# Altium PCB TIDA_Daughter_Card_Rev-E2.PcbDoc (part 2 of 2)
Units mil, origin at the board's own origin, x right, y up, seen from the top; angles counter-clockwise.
Board outline 3149.06 x 866.14 mil, 6 copper layers (L1-Top Layer, L2-GND1, L3-SIG1, L4-PWR, L5-GND2, L6-Bottom Layer), stack 0 mil thick; 80 components, 50 nets, 307 pads, 118 vias.
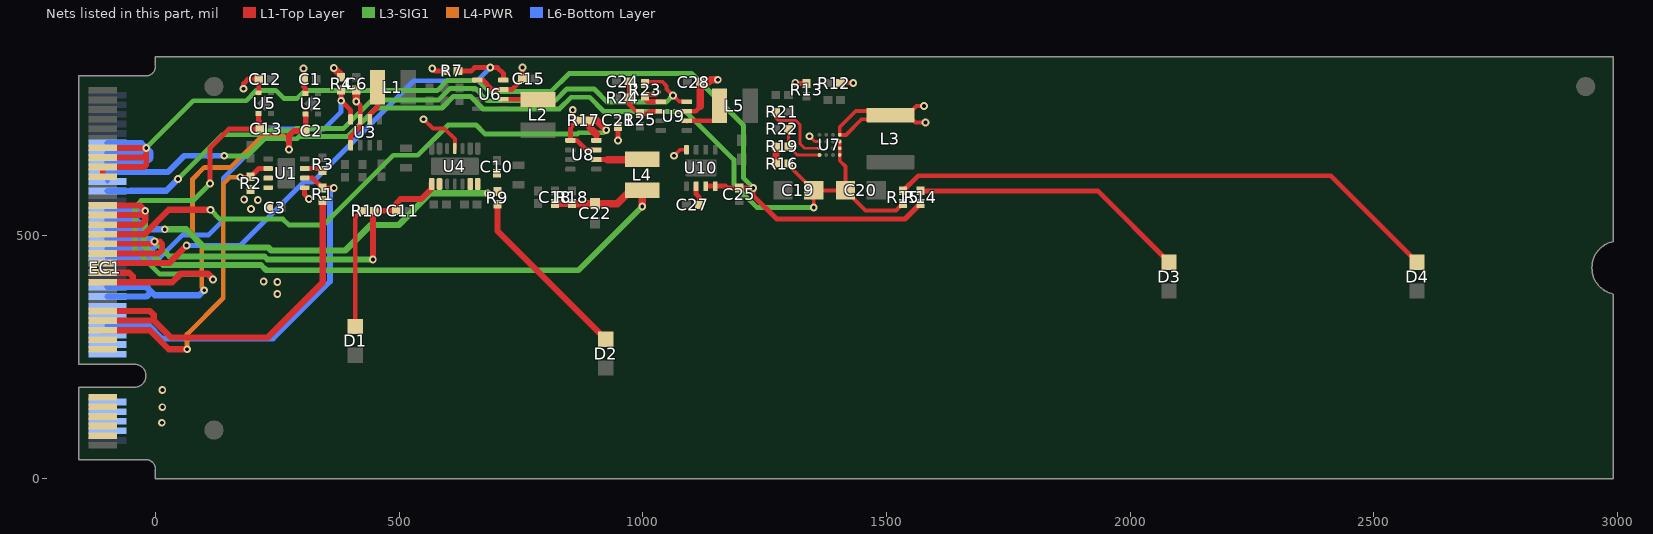
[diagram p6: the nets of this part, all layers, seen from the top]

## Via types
v1: diameter 16, hole 8, L1-Top Layer to L6-Bottom Layer, tented both sides, 111 vias
v2: diameter 19.68, hole 7.87, L1-Top Layer to L6-Bottom Layer, 7 vias

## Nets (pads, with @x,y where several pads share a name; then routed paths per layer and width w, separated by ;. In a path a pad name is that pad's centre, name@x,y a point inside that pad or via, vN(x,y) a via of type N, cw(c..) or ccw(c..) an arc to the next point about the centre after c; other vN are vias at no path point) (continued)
NetC24_2: C24.2 R24.1 R25.2 U9.2 | length 121.8
  L1-Top Layer w9: C24.2@971.99,815 R24.1@971.99,782 971.99,768.01 990.42,749.58 R25.2@994.57,749.58 1009.58,749.58 1014.31,754.31 U9.2@1037.22,754.31
NetC27_1: C27.1 U10.6 | length 41.3
  L1-Top Layer w10: U10.6@1109.44,600.6 1109.44,584.56 1115.99,578.01 C27.1@1115.99,562
NetD1_1: D1.1 R10.1 | length 242.9
  L1-Top Layer w10: D1.1@410,312.53 410,536.99 R10.1@423.01,550
NetD2_1: D2.1 R9.1 | length 368.9
  L1-Top Layer w12: R9.1@701.6,563.34 701.6,508.93 D2.1@924,286.53
NetD3_1: D3.1 R14.1 | length 570.7
  L1-Top Layer w10: R14.1@1570,591 1933.53,591 D3.1@2080,444.53
NetD4_1: D4.1 R15.1 | length 1141.2
  L1-Top Layer w10: R15.1@1534.12,591.05 1565.07,622 2411.53,622 D4.1@2589,444.53
NetL1_1: L1.1 U3.6 | length 72.9
  L1-Top Layer w10: U3.6@439.84,737.57 439.84,747.84 455.5,763.5 L1.1@455.5,804
NetL2_1: L2.1 U6.6 | length 71.4
  L1-Top Layer w10: U6.6@713.79,779 784.5,779 L2.1@785,778.5
NetL4_1: L4.1 U8.6 | length 94.5
  L1-Top Layer w10: U8.6@904.75,655.21 927.79,655.21 928,655
  L1-Top Layer w15: 928,655 998.5,655 L4.1@999,655.5
NetL5_1: L5.1 U9.6 | length 91.4
  L1-Top Layer w10: U9.6@1090.37,734.63 1090.61,734.87 1145.65,734.87 1157.5,746.73 L5.1@1157.5,766
NetR3_2: R3.2 U1.7 | length 38.6
  L1-Top Layer w10: U1.7@306,636.83 339.17,636.83 R3.2@343,633.01
NetR16_1: R16.1 R19.2 | length 35
  L1-Top Layer w15: R16.1@1273.45,647 R19.2@1273.45,682
NetR19_1: R19.1 R22.2 U7.A1@1362.83,664.58 | length 106.8
  L1-Top Layer w6: R22.2@1299,718 1299,682.44 R19.1@1299.43,682 1316.86,664.58 U7.A1@1362.83,664.58
NetR21_2: R21.2 U7.A2@1362.83,678.36 | length 150.8
  L1-Top Layer w6: R21.2@1273.02,753 1273.02,740.98 1279,735 1314.28,735 1323,726.28 1323,687 1331.64,678.36 U7.A2@1362.83,678.36
PG_VCC_3DNAND: EC1.54 R23.1 U9.8 | length 1392.4
  L1-Top Layer w8: R23.1@1005,810.99 1008.88,814.87 1040.13,814.87 1049.02,805.98 1049.02,799.87 v1(1062,786.89) 1074.89,774 U9.8@1090.37,774
  L3-SIG1 w10: v1(46,615) 137,706 210.28,706 217.98,713.7 283.82,713.7 288.69,718.57 385.66,718.57 444.78,777.7 580.95,777.7 604.52,801.27 655.8,801.27 681.07,776 820,776 844,800 900,800 926.87,773.13 1048.23,773.13 v1(1062,786.89)
  L6-Bottom Layer w13: EC1.54@-98.43,590.55 -51.89,590.55 -51.36,591.07 22.07,591.07 v1(46,615)
PG_VCC_DDR3: EC1.39 R7.1 U6.8 | length 1075.7
  L1-Top Layer w10: R7.1@620.99,837 647.81,837 654.81,844 v1(687,844) 701.76,844 713.79,831.97 U6.8@713.79,818.37
  L1-Top Layer w13: EC1.39@-108.27,442.91 27.91,442.91 v1(64,479)
  L6-Bottom Layer w10: v1(64,479) 174.39,479 304.51,609.13 322.66,609.13 530.53,817 660,817 v1(687,844)
PG_VCC_IO_3DNAND: EC1.45 R17.1 U8.8 | length 1250.2
  L1-Top Layer w10: U8.8@904.75,694.58 904.75,707.38
  L1-Top Layer w13: EC1.45@-108.27,501.97 -22.67,501.97 27.36,552 v1(113,552)
  L1-Top Layer w15: 904.75,707.38 891.74,720.39 R17.1@891.74,735.53 905.47,735.53 v1(925,716)
  L3-SIG1 w10: v1(113,552) 132,533 261.48,533 273.35,521.13 345.13,521.13 488,664 538.26,664 600.39,726.13 657.87,726.13 676,708 866,708 868.33,710.33 919.33,710.33 v1(925,716)
PG_VCORE_SOC: EC1.40 R4.1 U3.8 | length 745.6
  L1-Top Layer w10: R4.1@381,798.01 v1(381,775.92) 400.47,756.44 U3.8@400.47,737.57
  L6-Bottom Layer w10: EC1.40@-98.43,452.76 7.76,452.76 55,500 108.52,500 139.13,530.61 139.13,616.65 240.48,718 346,718 381,753 v1(381,775.92)
SSD_EN: EC1.25 R2.1 U1.2 | length 664.8
  L1-Top Layer w10: v1(174,619) 194.02,619 R2.1@195,619.98 211.85,636.83 U1.2@231.2,636.83
  L1-Top Layer w13: EC1.25@-108.27,305.12 -12.11,305.11 27,266 v1(65,266)
  L4-PWR w10: v1(65,266) 65,297 139,371 139,605.52 152.48,619 v1(174,619)
SSD_FLTb: EC1.26 R1.1 U1.6 | length 779.7
  L1-Top Layer w10: U1.6@306,617.15 322.84,617.15 R1.1@343,596.99 v1(366.01,596.99)
  L6-Bottom Layer w12: EC1.26@-98.43,314.96 -13.96,314.96 13,288 241,288 358,405 358,588.98 v1(366.01,596.99)
VAUX: EC1.27 EC1.29 R1.2 | length 799.9
  L1-Top Layer w13: EC1.27@-108.27,324.8 -3.8,324.8 ; EC1.29@-108.27,344.49 -11.93,344.49 -3.8,336.36 -3.8,324.8 ; R1.2@343,571.01 343,403 230,290 31,290 -3.8,324.8
VCC_3DNAND: C25.1 EC1.57 EC1.59 EC1.60 EC1.61 EC1.62 EC1.63 EC1.64 R14.2 U10.7 U10.8 | length 2601.6
  L1-Top Layer w10: U10.7@1129.13,600.6 U10.8@1148.81,600.6 1169.4,600.6 1173.01,596.99 C25.1@1198,596.99 v1(1226.7,596.99) 1226.7,581.3 1274.87,533.13 1538.11,533.13 R14.2@1570,565.02
  L1-Top Layer w12: EC1.57@-108.27,620.08 EC1.59@-108.27,639.76 -23.24,639.76 -19,644 -19,657.96 ; EC1.61@-108.27,659.45 -20.49,659.45 -19,657.96 ; EC1.63@-108.27,679.13 v1(-19,679.13) -19,657.96
  L3-SIG1 w10: v1(-19,679.13) 77.87,776 185.83,776 206.89,797.06 246.7,797.06 263.15,780.61 290.49,780.61 306.67,796.79 577.83,796.79 598.02,816.97 662.3,816.97 684.28,795 812,795 848.87,831.87 1100.13,831.87 1207,725 1207,616.7 v1(1226.7,596.99)
  L6-Bottom Layer w12: EC1.60@-98.43,649.61 -18.39,649.61 -9.87,658.13 -9.87,670.01 v1(-19,679.13) ; EC1.62@-98.43,669.29 -28.84,669.29 v1(-19,679.13) ; EC1.64@-98.43,688.98 -28.84,688.98 v1(-19,679.13)
VCC_DDR3: C10.1 EC1.46 EC1.48 R9.2 U4.13 U4.14 | length 929.1
  L1-Top Layer w15: C10.1@700.36,626.58 C10.1@700.79,627.01
  L3-SIG1 w13: v1(19,512) 63,512 100.4,474.6 231.31,474.6 237.39,468.53 389.53,468.53 442,521 499,521 564,586 v1(682,586)
  L6-Bottom Layer w13: EC1.46@-98.43,511.81 -98.43,512 -32.3,512 ; EC1.48@-98.43,531.5 -39.79,531.5 -32.3,524 -32.3,512 ; v1(19,512) -32.3,512
VCC_IO_3DNAND: C18.1 C22.1 EC1.47 EC1.49 EC1.50 EC1.51 L4.2 R18.2 | length 1766.4
  L1-Top Layer w13: EC1.47@-108.27,521.65 -29.43,521.65 -21,530.09 v1(-21,550) ; EC1.49@-108.27,541.34 -29.66,541.34 v1(-21,550) ; EC1.51@-108.27,561.02 -32.02,561.02 v1(-21,550)
  L1-Top Layer w15: C18.1@820,565.01 R18.2@855,565.01 855.32,564.68 C22.1@902,564.68 947.56,564.68 975.38,592.5 L4.2@999,592.5 v1(999,559)
  L3-SIG1 w12: v1(-21,550) -21,498.93 -23.87,496.06 -23.87,477.94 15.37,438.7 216.44,438.7 227.02,428.13 868.13,428.13 v1(999,559)
  L6-Bottom Layer w13: EC1.50@-98.43,551.18 -22.18,551.18 v1(-21,550)
VCC_IO_SOC: C13.1 EC1.35 EC1.37 U5.1 | length 987.7
  L1-Top Layer w10: v1(112,606) 112,679 151,718 C13.1@214.01,718 214.01,733.74 211.31,736.44 U5.1@211.31,750.01
  L1-Top Layer w13: EC1.35@-108.27,403.54 -47,403.54 ; EC1.37@-108.27,423.23 -54.23,423.23 -47,416 -47,403.54 ; v1(118,409) 118,410 106.63,421.37 52.37,421.37 34.54,403.54 -47,403.54
  L3-SIG1 w10: v1(112,606) 77,571 -29.52,571 -41.87,558.65 -41.87,470.91 9.03,420 108,420 118,410 v1(118,409)
VCC_SOC: C2.1 EC1.32 EC1.34 U2.1 | length 898
  L1-Top Layer w12: v1(274,676) 274,704 283.82,713.82 C2.1@306.85,713.82 308.24,715.2 U2.1@308.24,748.75
  L4-PWR w10: v1(100.13,386.94) 94.87,392.19 94.87,480.13 76,499 76,615 100,639 154.52,639 219.39,703.87 262.13,703.87 274,692 v1(274,676)
  L6-Bottom Layer w13: EC1.32@-98.43,374.02 -18.42,374.02 -8.63,383.81 ; EC1.34@-98.43,393.7 -18.52,393.7 -8.63,383.81 ; v1(100.13,386.94) 89.82,376.63 -1.44,376.63 -8.63,383.81
VCORE_SOC: C11.1 EC1.41 EC1.42 EC1.43 EC1.44 R10.2 U4.8 U4.9 | length 1203.3
  L1-Top Layer w12: EC1.41@-108.27,462.6 6.6,462.6 14,470 14,482 9,487 v1(-2,487) -6.72,482.28 EC1.43@-108.27,482.28 ; v1(446,450) 446,550 R10.2@448.99,550 ; R10.2@448.99,550 C11.1@494.01,550 494.01,565.01 503,574 545,574 U4.8@566.54,595.54 ; U4.8@566.54,606.58 U4.8@566.54,595.54 ; U4.8@567.01,605 567.01,596.01 U4.8@566.54,595.54
  L3-SIG1 w12: v1(-2,487) 28.6,456.4 223.77,456.4 230.17,450 v1(446,450)
  L6-Bottom Layer w12: EC1.42@-98.43,472.44 -5.56,472.44 -2,476 v1(-2,487) -7.13,492.13 EC1.44@-98.43,492.13
VIN: C3.1 EC1.3 EC1.4 EC1.5 EC1.6 EC1.7 EC1.8 EC1.9 EC1.10 EC1.11 EC1.20 EC1.21 EC1.22 EC1.23 EC1.24 R2.2 U1.3 U1.4
  other v1: 13,115 14,147 14,182 196,554 210,572 182,573
VPP_3DNAND: C19.1 C20.1 EC1.56 EC1.58 R15.2 R16.2 U7.D1@1404.17,664.58 U7.D2@1404.17,678.36 U7.D3@1404.17,692.13 | length 2100.3
  L1-Top Layer w8: R16.2@1299.43,647 1299.43,643.51 C19.1@1350.94,592 ; v1(1350.94,556.94) C19.1@1350.94,592 ; U7.D3@1404.17,692.13 U7.D2@1404.17,678.36 U7.D1@1404.17,664.58 1404.17,652.82 1415.95,641.04 C20.1@1415.95,592 ; R15.2@1534.12,565.06 1520.05,551 1456.95,551 C20.1@1415.95,592 ; C19.1@1350.94,592 C20.1@1415.95,592
  L3-SIG1 w10: v1(141,663) 141.89,662.11 188.59,662.11 224.48,698 290.32,698 295.19,702.87 394.87,702.87 453,761 587.86,761 611.44,784.57 646.56,784.57 672.14,759 828.81,759 852.81,783 891,783 920.43,753.57 1088.43,753.57 1187,655 1187,604 1234.06,556.94 v1(1350.94,556.94)
  L6-Bottom Layer w8: EC1.56@-98.43,610.24 EC1.58@-98.43,629.92
  L6-Bottom Layer w12: EC1.58@-98.43,629.92 25.92,629.92 59,663 v1(141,663)
VSYS: C1.1 C6.1 C12.1 C15.1 C21.1 C28.1 EC1.28 EC1.30 L3.1 R4.2 R7.2 R12.2 R13.1 R17.2 R23.2 U1.5 U2.4 U3.1 U3.7 U4.4 U5.4 U6.1 U6.7 U7.A3@1362.83,692.13 U7.D4@1404.17,705.91 U8.1 U8.7 U9.1 U9.7 U10.4 | length 1405.1
  L1-Top Layer w6: v1(1342.15,703) 1353.02,692.13 U7.A3@1362.83,692.13
  L1-Top Layer w8: v1(550,738) 569.3,718.7 592.64,718.7 614.25,697.09 U4.4@614.25,677.83 ; v1(1064,663) 1076.4,675.4 U10.4@1089.76,675.4 ; R12.2@1406,812 v1(1432,812) ; v1(1577,765) 1562,765 L3.1@1543.23,746.23 ; v1(1580,731) 1560,731 1544.77,746.23 L3.1@1543.23,746.23 ; L3.1@1508,746.23 L3.1@1543.23,746.23 ; L3.1@1508,746.23 1499.23,755 1437,755 1404.17,722.17 U7.D4@1404.17,705.91 1416.91,705.91 1449,738 1499.77,738 L3.1@1508,746.23
  L1-Top Layer w10: v1(180.8,800.48) 180.8,810.95 190.33,820.48 C12.1@211.8,820.48 211.8,792.63 U5.4@211.31,792.13 ; v1(304.01,841.84) C1.1@304.01,820 304.01,804.65 308.24,800.43 U2.4@308.24,790.87 ; U1.5@306,597.46 306,583 v1(315,574) ; U3.1@400.47,684.43 400.47,702.47 420.16,722.16 U3.7@420.16,737.57 420.16,766.28 v1(412,774.44) ; v1(568,842) 573,837 R7.2@595.01,837 ; U6.1@660.64,818.37 671.79,818.37 691.47,798.69 U6.7@713.79,798.69 730.7,798.69 C15.1@753.02,821 v1(753.02,844) ; v1(856.33,757) 856.33,744.96 R17.2@865.76,735.53 851.6,721.37 U8.1@851.6,694.58 864.42,694.58 884.1,674.9 U8.7@904.75,674.9 ; v1(949.36,694.3) C21.1@949.36,723.01 ; v1(1028,794) 1031,794 1026,789 1008.99,789 R23.2@1005,785.01 1005,779 1010,774 U9.1@1037.22,774 ; U9.7@1090.37,754.31 1108.32,754.31 1117.99,763.99 ; v1(1313,813) 1315.01,810.99 R13.1@1336,810.99
  L1-Top Layer w15: v1(366,843) 381,828 R4.2@381,823.99 ; v1(412,774.44) C6.1@412,798.02 ; 1117.99,763.99 C28.1@1117.99,814 1134.22,814 1139.22,819 v1(1154,819)
  other v1: 250,379 250,404 222,405
pads on no net: FID1.1 FID2.1 FID3.1 U1.9@268.6,609.28 U1.9@268.6,644.71 U3.4 U4.15@588.46,641.42 U4.15@640.04,641.42 U6.4 U7.A1@1362.83,664.58 U7.A2@1362.83,678.36 U7.A3@1362.83,692.13 U7.A4@1362.83,705.91 U7.B1@1376.61,664.58 U7.B2@1376.61,678.36 U7.B3@1376.61,692.13 U7.B4@1376.61,705.91 U7.C1@1390.39,664.58 U7.C2@1390.39,678.36 U7.C3@1390.39,692.13 U7.C4@1390.39,705.91 U7.D1@1404.17,664.58 U7.D2@1404.17,678.36 U7.D3@1404.17,692.13 U7.D4@1404.17,705.91 U8.4 U9.4 U10.9@1101.57,638 U10.9@1137,638

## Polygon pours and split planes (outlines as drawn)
VCC_DDR3 on L1-Top Layer "L1-TOP_LAYER_VCC_DDR3_P056" (solid, remove dead copper, pour order 56): 718,637 724.29,630.71 724.29,582.29 721,579 646,579 639.38,585.62 639.38,617.07 642.31,620 676,620 676,622 691,637
VIN on L1-Top Layer "L1-TOP_LAYER_VIN_P054" (solid, remove dead copper, pour order 54): 184,604 212,604 219,611 219,620 222,623 241,623 244,620 244,582 242,580 242,565.99 219.01,543 184.05,543 175,552.05 175,595
GND on L1-Top Layer "L1-TOP_LAYER_GND_P048" (solid, remove dead copper, pour order 48): 1370,138 1370,775 1446,851 2842,851 2925,768 2925,97 2867.37,39.37 1468.63,39.37
GND on L1-Top Layer "L1-TOP_LAYER_GND_P046" (solid, remove dead copper, pour order 46): 86,58.69 86,200 286,400 1141,400 1224,317 1224,41 1195,12 1193,14 130.69,14
GND on L1-Top Layer "L1-TOP_LAYER_GND_P026" (solid, remove dead copper, pour order 26): -140,692 -138,690 -61,690 20,771 20,798 5,813 -134,813 -140,807
VIN on L1-Top Layer "L1-TOP_LAYER_VIN_P000" (solid, remove dead copper, pour order 0): -140,250.53 -138.53,250.53 -137,249 -21.72,249 -3,230.28 -3,191 -19,175 -138,175 -140,173 -140,85 10,85 35,110 35,240 -18,293 -137,293 -140,290
GND on L6-Bottom Layer "L6-BOTTOM_LAYER_GND_P052" (solid, remove dead copper, pour order 52): 55,24 24,55 -138,55 -148,65 -148,171 -137,182 -14.85,182 -5,191.85 -5,235 -16,246 -145,246 -150,251 -150,807 -139,818 -6,818 33,857 2957,857 2979,835 2979,515 2930,466 2930,404 2974,360 2974,57 2941,24
GND on L6-Bottom Layer "L6-BOTTOM_LAYER_GND_P032" (solid, remove dead copper, pour order 32): -142,702.17 -140,700.17 -57.83,700.17 7,765 7,790 -13,810 -135,810 -142,803
VIN on L6-Bottom Layer "L6-BOTTOM_LAYER_VIN_P002" (solid, remove dead copper, pour order 2): -21.85,175 -1,195.85 -1,228 -21.36,248.36 -24.72,245 -134.47,245 -140,250.53 -140,300 -135,305 -29,305 35,241 35,110 18.51,93 -140,93 -140,165 -130,175
VSYS on L6-Bottom Layer "L6-BOTTOM_LAYER_VSYS_P006" (solid, remove dead copper, pour order 6): 56.65,365 82.62,339.02 118.02,339.02 194,415 253,415 268,400 268,383 177,292 49,292 16,325 -140,325 -145,330 -145,360 -140,365
VIN on L4-PWR "L4-PWR_VIN_P004" (solid, remove dead copper, pour order 4): 165.12,587.12 150,572 150,339 0,189 0,115 13,102 33,102 166,235 166,289 198,321 198,524 219,545 219,576 207.88,587.12
VSYS on L4-PWR "L4-PWR_VSYS_P024" (solid, remove dead copper, pour order 24): 184,224 184,274 211.49,301.49 211.49,397 211.49,515.49 233,537 233,584 217,600 160,600 141,619 141,797 203.99,859.99 2949.91,860.08 2975,835 2975,522 2925,472 2925,397 2970,352 2970,57 2938,25 234.01,25 184,75
GND on L3-SIG1 "L3-SIG1_GND_P050" (solid, remove dead copper, pour order 50): 55,24 24,55 -138,55 -148,65 -148,171 -137,182 -14.85,182 -5,191.85 -5,235 -16,246 -145,246 -150,251 -150,807 -139,818 -6,818 33,857 2957,857 2979,835 2979,515 2930,466 2930,404 2974,360 2974,57 2941,24
GND on L5-GND2 "L5-GND2_GND_P034" (solid, remove dead copper, pour order 34): 55,24 27,52 -135,52 -148,65 -148,171 -137,182 -20.17,182 -5,197.17 -5,235 -16,246 -145,246 -150,251 -150,807 -139,818 -6,818 33,857 2957,857 2979,835 2979,515 2930,466 2930,404 2974,360 2974,57 2941,24
GND on L2-GND1 "L2-GND1_GND_P044" (solid, remove dead copper, pour order 44): 55,24 24,55 -138,55 -148,65 -148,171 -137,182 -14.85,182 -5,191.85 -5,235 -16,246 -145,246 -150,251 -150,807 -139,818 -6,818 33,857 2957,857 2979,835 2979,515 2930,466 2930,404 2974,360 2974,57 2941,24

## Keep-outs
Keep-Out Layer:
  text ".Layer_Name" at 418.57,-2692.59 h60

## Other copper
L1-Top Layer:
  text ".Layer_Name" at 418.57,-2691.59 h60
  text ".Layer_Name" at 418.57,-2692.59 h60
L2-GND1:
  text ".Layer_Name" at 418.57,-2692.59 h60
L3-SIG1:
  text ".Layer_Name" at 418.57,-2694.59 h60
L4-PWR:
  pour cut-out: 288,683.02 288,674 297.4,674 297.04,683.02
  text ".Layer_Name" at 418.57,-2691.59 h60
L5-GND2:
  text ".Layer_Name" at 418.57,-2694.59 h60
L6-Bottom Layer:
  pour cut-out: 196.23,419 191.15,425 261.84,425 279,407.84 279,379.24 228.77,329.12 227.64,343.64 270.32,386.32 270.32,403 259.22,419
  pour cut-out: -141,93 27.18,93 41.49,107.31 41.49,242.51 21.43,262.57 21.43,265.9 24.53,269 43,269 51,261 51,98 35,82 -8,82 -9.96,83.96 -141,83.96
  text ".Layer_Name" at 418.57,-2692.59 h60

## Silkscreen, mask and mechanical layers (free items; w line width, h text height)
Top Overlay:
  lines w6: 192,49 665,49 665,521 192,521 192,49 ; 717,52 717,392 1123,392 1123,52 717,52 ; 1812,50 1812,752 2335,752 2335,50 1812,50 ; 2355,50 2877,50 2877,753 2355,753 2355,50
  text "'.PRJ_Number' .PCB_Rev" at 1976,784 h90
  text "NAND" at 2001,86 h40
  text "NAND" at 2530,86 h40
  text "CONTROLLER" at 259,72 h40
  text "DDR3" at 857,70 h40
  text ".Layer_Name" at 418.57,-2692.59 h60
Bottom Overlay:
  text ".Layer_Name" at 418.57,-2692.59 h60
Top Paste:
  text ".Layer_Name" at 418.57,-2692.59 h60
Bottom Paste:
  text ".Layer_Name" at 418.57,-2692.59 h60
Top Solder:
  text ".Layer_Name" at 418.57,-2692.59 h60
  text ".Layer_Name" at 418.57,-2692.59 h60
Bottom Solder:
  text ".Layer_Name" at 418.57,-2692.59 h60
Drill Guide:
  text ".Layer_Name" at 418.57,-2692.59 h60
M1 Board Outline:
  lines w5: 47.24,0 2991.18,0 2991.58,0.39 2991.58,379.24 ; 47.24,866.14 2991.58,866.14 2991.58,865.75 2991.58,486.9 ; 2991.54,379.24 cw(c3002.82,433.07) 2991.54,486.9
M2 Board Dimensions:
  rectangle: -158.43,-2109.09 -33.43,-1984.09
  rectangle: -33.43,-2234.09 341.57,-2109.09
  lines w7: -158.43,-2109.09 841.57,-2109.09 ; -33.43,-2234.09 -33.43,-1984.09 ; 91.57,-2234.09 91.57,-1984.09 ; 341.57,-2234.09 341.57,-1984.09 ; 591.57,-2234.09 591.57,-1984.09 ; -158.43,-2234.09 841.57,-2234.09 841.57,-1984.09 -158.43,-1984.09 -158.43,-2234.09
M3 3D STEP Top:
  text ".Layer_Name" at 418.57,-2692.59 h60
M4 3D STEP Bottom:
  text ".Layer_Name" at 418.57,-2692.59 h60
M5 Assembly Top:
  lines w10: -450.43,-2764.26 6149.57,-2764.26 ; -450.43,-2560.93 6151.57,-2560.93 ; -450.43,-2357.59 -450.43,-2967.59 3554.57,-2967.59 6151.57,-2967.59 6151.57,-2357.59 -449.93,-2357.59 -449.93,-2967.59 1125.57,-2967.59 ; 2014.57,-2967.59 2014.57,-2357.59 ; 3281.57,-2560.93 3281.57,-2357.59 ; 4121.57,-2560.93 4121.57,-2357.59 ; 4743.57,-2974.09 4743.57,-2771.26
  text "COMPONENTS MARKED 'DNP' SHOULD NOT BE POPULATED." at 995.07,-2152.59 h60
  text "ASSEMBLY VARIANT:" at 994.57,-2268.09 h60
  text ".VariantName" at 2030.57,-2268.09 h60
  text "PCB VIEWED FROM TOP SIDE" at -386.93,-2489.76 h60
  text "BOARD #:" at 2089.57,-2489.76 h60
  text ".PRJ_Number" at 2635.07,-2489.76 h60
  text "REV:" at 3479.57,-2489.76 h60
  text ".PCB_Rev" at 3771.07,-2489.76 h60
  text "SVN REV:" at 4317.57,-2489.76 h60
  text ".VersionControl_RevNumber" at 4823.57,-2489.76 h60
  text "LAYER NAME =" at -386.93,-2692.59 h60
  text "TID #:" at 2089.57,-2693.09 h60
  text ".TID" at 2635.07,-2693.09 h60
  text ".Layer_Name" at 417.57,-2696.59 h60
  text "PLOT NAME =" at -386.93,-2898.43 h60
  text ".plot_File_Name" at 418.57,-2898.43 h60
  text "GENERATED    :" at 2091.57,-2898.43 h60
  text ".Print_Date" at 2961.07,-2898.43 h60
  text ".Print_Time" at 3690.07,-2898.43 h60
  text "TEXAS INSTRUMENTS" at 4954.57,-2898.43 h60
M6 Assembly Bottom:
  lines w10: -450.93,-2561.43 6151.07,-2561.43 ; -448.93,-2764.76 6151.07,-2764.76 ; 957.07,-2974.59 957.07,-2771.76 ; 1579.07,-2561.43 1579.07,-2358.09 ; 2419.07,-2561.43 2419.07,-2358.09 ; 3686.07,-2968.09 3686.07,-2358.09 ; 4575.07,-2968.09 6150.57,-2968.09 6150.57,-2358.09 -450.93,-2358.09 -450.93,-2968.09 2146.07,-2968.09 6151.07,-2968.09 6151.07,-2358.09
  text "COMPONENTS MARKED 'DNP' SHOULD NOT BE POPULATED." at 5943.57,-2152.09 h60
  text ".VariantName" at 4899.57,-2268.09 h60
  text "ASSEMBLY VARIANT:" at 5938.57,-2268.09 h60
  text ".VersionControl_RevNumber" at 877.07,-2490.26 h60
  text "SVN REV:" at 1383.07,-2490.26 h60
  text ".PCB_Rev" at 1929.57,-2490.26 h60
  text "REV:" at 2221.07,-2490.26 h60
  text ".PRJ_Number" at 3065.57,-2490.26 h60
  text "BOARD #:" at 3611.07,-2490.26 h60
  text "PCB VIEWED FROM BOTTOM SIDE" at 6087.57,-2490.26 h60
  text ".TID" at 3065.57,-2693.59 h60
  text "TID #:" at 3611.07,-2693.59 h60
  text "TEXAS INSTRUMENTS" at 746.07,-2898.93 h60
  text ".Print_Time" at 2010.57,-2898.93 h60
  text ".Print_Date" at 2739.57,-2898.93 h60
  text "GENERATED    :" at 3609.07,-2898.93 h60
  text ".plot_File_Name" at 5282.07,-2898.93 h60
  text "PLOT NAME =" at 6087.57,-2898.93 h60
M9 Title Sheet:
  drawing of 57 lines, arcs and shapes, not listed
  text "1" at 581.41,6202.41 h70
  text "2" at 3077.07,6202.41 h70
  text "3" at 5566.42,6202.41 h70
  text "4" at 8073.09,6202.41 h70
  text "5" at 10572.07,6202.41 h70
  text "6" at 13077.07,6202.41 h70
  text "A" at -574.93,5059.41 h70
  text "A" at 14225.07,5059.41 h70
  text "B" at -574.93,2679.41 h70
  text "B" at 14225.07,2679.41 h70
  text "C" at -574.93,304.41 h70
  text "C" at 14225.07,304.41 h70
  text "PROJECT TITLE:" at 11185.07,-1556.59 h45
  text ".PRJ_Title" at 11235.07,-1689.92 h45
  text "DESIGNED FOR:" at 11185.07,-1857.59 h45
  text ".PRJ_Customer" at 11235.07,-1997.59 h70
  text "D" at -574.93,-2065.59 h70
  text "D" at 14225.07,-2065.59 h70
  text "FILE NAME:" at 11185.07,-2157.59 h45
  text ".PCB_File_Name_No_Path" at 11235.07,-2277.59 h70
  text "Texas Instruments (TI) and/or its licensors do not warrant the accuracy or completeness of this specification" at 6215.57,-2439.43 h45
  text "ENGINEER:" at 11185.07,-2447.59 h45
  text "LAYOUT BY:" at 12690.07,-2447.59 h45
  text "or any information contained therein. TI and/or its licensors do not warrant that this design will meet" at 6170.59,-2552.1 h45
  text ".PRJ_Engineer" at 11235.07,-2602.59 h70
  text ".PCB_Layout" at 12740.57,-2602.59 h70
  text "the specifications, will be suitable for your application or fit for any particular purpose, or will operate in" at 6170.59,-2664.76 h45
  text "ALTIUM DESIGNER VERSION:" at 12690.07,-2757.59 h45
  text "an implementation. TI and/or its licensors do not warrant that the design is production worthy. You should" at 6170.59,-2777.43 h45
  text "completely validate and test your design implementation to confirm the system functionality for your application." at 6215.57,-2890.09 h45
  text ".print_Scale" at 11235.07,-2890.92 h70
  text ".Application_BuildNumber" at 12740.57,-2890.92 h70
  text "1" at 581.41,-3097.59 h70
  text "2" at 3077.07,-3097.59 h70
  text "3" at 5566.42,-3097.59 h70
  text "4" at 8073.09,-3097.59 h70
  text "5" at 10572.07,-3097.59 h70
  text "6" at 13077.07,-3097.59 h70
M10 Fab Notes:
  drawing of 189 lines, arcs and shapes, not listed
  text "DESIGN INFORMATION" at 12223.59,4522.08 h60
  text "MIN. TRACK WIDTH:" at 11579.03,4389.95 h60
  text "6" at 12675.28,4389.96 h60
  text "MIL" at 12830.03,4389.95 h60
  text "mm" at 12843,4270 h60
  text "MIN. CLEARANCE:" at 11579.03,4265.83 h60
  text "0.12" at 12615.28,4265.83 h60
  text "MIN. VIA PAD SIZE:" at 11579.03,4141.7 h60
  text "16" at 12645.29,4141.7 h60
  text "MIL" at 12830.03,4141.7 h60
  text "0.05mm (4MIL)" at 12274.03,4011.8 h60
  text "MINIMUM ANNULAR RING" at 11249.8,4003.58 h60
  text "EXTERNAL" at 12982.03,4003.58 h60
  text "PER" at 11449.8,3893.45 h60
  text "IPC-D-275 CLASS 2 LEVEL C" at 11669.8,3893.45 h60
  text "MIL, HOLES" at 13158.03,3792.97 h60
  text "+/-" at 12765.57,3784.39 h60
  text "+/-" at 13619.57,3784.39 h60
  text "REGISTRATION TOLERANCES:" at 11249.8,3783.32 h60
  text "METAL" at 12449.57,3783.32 h60
  text "5" at 13025.78,3783.33 h60
  text "3" at 13858.78,3783.33 h60
  text "MIL" at 13975.03,3783.32 h60
  text "HOLE SIZE TOLERANCE (UNLESS OTHERWISE SPECIFIED):" at 11249.8,3685.01 h60
  text "+/-" at 13619.57,3682.14 h60
  text "3" at 13858.78,3681.08 h60
  text "MIL" at 13975.03,3681.07 h60
  text "MATERIAL:" at 11175.03,3543.43 h60
  text "FR-4 High Tg" at 12161.48,3414.9 h60
  text "X" at 12017.04,3406.91 h60
  text "FR-408" at 11596.04,3402.39 h60
  text "OTHER" at 13084.03,3402.39 h60
  text "X" at 11796.04,3256.91 h60
  text "31.49MIL (0.8mm) +/-10%" at 11898,3254 h60
  text "THICKNESS:" at 11249.8,3251.14 h60
  text "OTHER" at 13201.03,3251.14 h60
  text "TOLERANCE:" at 11249.8,3112.83 h60
  text "X" at 12098.04,3112.83 h60
  text "ANSI IPC-6012 TYPE 3 CLASS 2" at 12276.05,3112.83 h60
  text "OTHER +/-" at 12276.03,2968.64 h60
  text "BOW & TWIST:" at 11249.8,2823.45 h60
  text "X" at 12098.04,2823.45 h60
  text "ANSI IPC-6012 TYPE 3 CLASS 2" at 12276.05,2823.45 h60
  text "OTHER +/-" at 12276.03,2676.75 h60
  text "DRILLING:" at 11175.03,2546.14 h60
  text "NC_DRILL FILES" at 12936.03,2440.95 h60
  text "REFERENCE:" at 11249.8,2437.01 h60
  text "X" at 11907.04,2436.91 h60
  text "AS SHOWN" at 12085.03,2437.01 h60
  text "X" at 12808.04,2437.01 h60
  text "OTHER" at 13234.03,2294.76 h60
  text "PTH COPPER THICKNESS:" at 11249.48,2291.23 h60
  text "X" at 12388.72,2291.23 h60
  text "20-30 um" at 12516.71,2291.23 h60
  text "BOARD FINISH:" at 11175.03,2143.63 h60
  text "SILKSCREEN:" at 11330.26,2033.51 h60
  text "X" at 12288.04,2033.51 h60
  text "TOP" at 12405.03,2033.51 h60
  text "BOTTOM" at 12916.03,2033.51 h60
  text "SILKSCREEN COLOR:" at 11330.26,1878.32 h60
  text "X" at 12287.04,1878.32 h60
  text "WHITE" at 12405.03,1878.32 h60
  text "OTHER" at 12916.03,1878.32 h60
  text "X" at 12418.04,1734.87 h60
  text "GREEN" at 12536.03,1734.87 h60
  text "OTHER" at 13154.03,1734.87 h60
  text "SOLDER RESIST COLOR:" at 11330.26,1728 h60
  text "X" at 12418.04,1580.62 h60
  text "MATTE" at 12536.03,1580.62 h60
  text "SEMI-GLOSS" at 13153.57,1579.98 h60
  text "IMMERSION GOLD (ENIG)" at 12236.03,1407.84 h60
  text "ENEPIG" at 13573.57,1400.62 h60
  text "SURFACE FINISH:" at 11175.03,1399.62 h60
  text "X" at 12058.04,1399.62 h60
  text "IMM. TIN/SILVER OR EQUIV" at 11504.57,1262.31 h60
  text "OTHER" at 12936.03,1258.37 h60
  text "ARRAY/PANEL:" at 11175.03,1102.99 h60
  text "X" at 12049,1098 h60
  text "CUT AND TRIM PER M1 BOARD OUTLINE" at 12236.03,1094.77 h60
  text "N.C. ROUTE" at 12236.03,958.8 h60
  text "V. SCORE" at 13102.03,958.8 h60
  text "CERTIFICATION:" at 11175.03,829.68 h60
  text "MATERIALS AND WORKMANSHIP FOR ALL PCBS" at 11900.03,829.68 h60
  text "TO MEET OR EXCEED THE REQUIREMENTS OF:" at 11900.03,735.61 h60
  text "X" at 11537.54,606.99 h60
  text "ANSI IPC-A-600F CLASS ->" at 11665.54,606.99 h60
  text "X" at 13313.54,606.99 h60
  text "2" at 13423.54,606.99 h60
  text "1" at 13108.54,605.49 h60
  text "3" at 13777.54,605.49 h60
  text "X" at 12349.54,459.3 h60
  text "RoHS" at 12477.54,459.3 h60
  text "OTHER" at 13121.94,459.3 h60
  text "PER ORDER" at 13519,459.3 h60
  text "NOTE:" at 5101,362 h40
  text "ALL BOARDS MUST MEET OR EXCEED UL94-V0 REQUIREMENTS." at 11202.57,305.47 h60
  text "THIS IS NOT AN IMPEDANCE CONTROL BOARD" at 5103,278 h40
  text "ALL VIAS ARE TENTED EXCEPT ON-PAD VIAS" at 5107,210 h40
  text "PCB MUST BEAR THE UL94V-0 UL REGISTERED MATERIAL ID NUMBER" at 11202.57,189.41 h60
  text "BOARD THICKNESS IS 0.8MM, DIELCTRIC THICKENSS CAN BE ADJUSTED BY FAB VENDOR." at 5105,134 h40
  text "ADDITIONAL REQUIREMENTS:" at 11175.03,19.99 h60
  text "MICROSECTION:" at 11249.8,-87.14 h60
  text "YES" at 12155.54,-87.14 h60
  text "REQUIRED" at 13017.03,-231.47 h60
  text "BARE BOARD ELEC. TEST:" at 11249.8,-234.33 h60
  text "NONE" at 12555.54,-234.33 h60
  text "X" at 12899.04,-234.33 h60
  text "PER ORDER" at 13609.03,-234.33 h60
  text "XX MIL VIAS REQUIRE NON-CONDUCTIVE FILL AND PLANARIZE" at 11417.95,-439.28 h59
  text "XX MIL VIAS REQUIRE CONDUCTIVE FILL AND PLANARIZE" at 11425.95,-543.25 h60
  text "OUTER XX MIL TRACES REQUIRE 50 OHM SINGLE-ENDED IMPEDANCE" at 11429,-706 h52
  text "LAYER 2 & 3 (INNER LAYERS) XX MIL WIDE, XX MIL SPACE / TRACES REQUIRE 100 OHM DIFFERENTIAL IMPEDANCE" at 11416.97,-942.35 h60
M11 Gerber Information:
  lines w10: -450.43,-2764.26 6149.57,-2764.26 ; -450.43,-2560.93 6151.57,-2560.93 ; -450.43,-2357.59 -450.43,-2967.59 3554.57,-2967.59 6151.57,-2967.59 6151.57,-2357.59 -449.93,-2357.59 -449.93,-2967.59 1125.57,-2967.59 ; 2014.57,-2967.59 2014.57,-2357.59 ; 3281.57,-2560.93 3281.57,-2357.59 ; 4121.57,-2560.93 4121.57,-2357.59 ; 4743.57,-2974.09 4743.57,-2771.26
  text "ALL ARTWORK VIEWED FROM TOP SIDE" at -386.93,-2489.76 h60
  text "BOARD #:" at 2089.57,-2489.76 h60
  text ".PRJ_Number" at 2635.07,-2489.76 h60
  text "REV:" at 3479.57,-2489.76 h60
  text ".PCB_Rev" at 3771.07,-2489.76 h60
  text "SVN REV:" at 4317.57,-2489.76 h60
  text ".VersionControl_RevNumber" at 4823.57,-2489.76 h60
  text "LAYER NAME =" at -386.93,-2692.59 h60
  text "TID #:" at 2089.57,-2693.09 h60
  text ".TID" at 2635.07,-2693.09 h60
  text "PLOT NAME =" at -386.93,-2898.43 h60
  text ".plot_File_Name" at 418.57,-2898.43 h60
  text "GENERATED    :" at 2091.57,-2898.43 h60
  text ".Print_Date" at 2961.07,-2898.43 h60
  text ".Print_Time" at 3690.07,-2898.43 h60
  text "TEXAS INSTRUMENTS" at 4954.57,-2898.43 h60
M12 Stackup:
  drawing of 317 lines, arcs and shapes, not listed
  text "Layer" at 6811.17,5822.5 h60
  text "Name" at 7159.41,5822.5 h60
  text "Material" at 8013.54,5822.5 h60
  text "Thickness" at 8676,5822.5 h60
  text "Constant" at 9189.92,5822.5 h60
  text "Board Layer Stack" at 9682.7,5822.5 h60
  text "1" at 6811.17,5702.5 h60
  text "Top Overlay" at 7159.41,5702.5 h60
  text "2" at 6811.17,5582.5 h60
  text "Top Solder" at 7159.41,5582.5 h60
  text "Solder Resist" at 8013.54,5582.5 h60
  text "0" at 9189.92,5582.5 h60
  text "3" at 6811.17,5462.5 h60
  text "L1-Top Layer" at 7159.41,5462.5 h60
  text "Copper" at 8013.54,5462.5 h60
  text "4" at 6811.17,5342.5 h60
  text "Dielectric 3" at 7159.41,5342.5 h60
  text "0" at 9189.92,5342.5 h60
  text "5" at 6811.17,5222.5 h60
  text "L2-GND1" at 7159.41,5222.5 h60
  text "Copper" at 8013.54,5222.5 h60
  text "6" at 6811.17,5102.5 h60
  text "Dielectric 2" at 7159.41,5102.5 h60
  text "0" at 9189.92,5102.5 h60
  text "7" at 6811.17,4982.5 h60
  text "L3-SIG1" at 7159.41,4982.5 h60
  text "Copper" at 8013.54,4982.5 h60
  text "8" at 6811.17,4862.5 h60
  text "Dielectric 4" at 7159.41,4862.5 h60
  text "0" at 9189.92,4862.5 h60
  text "9" at 6811.17,4742.5 h60
  text "L4-PWR" at 7159.41,4742.5 h60
  text "Copper" at 8013.54,4742.5 h60
  text "10" at 6811.17,4622.5 h60
  text "Dielectric 5" at 7159.41,4622.5 h60
  text "0" at 9189.92,4622.5 h60
  text "11" at 6811.17,4502.5 h60
  text "L5-GND2" at 7159.41,4502.5 h60
  text "Copper" at 8013.54,4502.5 h60
  text "12" at 6811.17,4382.5 h60
  text "Dielectric1" at 7159.41,4382.5 h60
  text "0" at 9189.92,4382.5 h60
  text "13" at 6811.17,4262.5 h60
  text "L6-Bottom Layer" at 7159.41,4262.5 h60
  text "Copper" at 8013.54,4262.5 h60
  text "14" at 6811.17,4142.5 h60
  text "Bottom Solder" at 7159.41,4142.5 h60
  text "Solder Resist" at 8013.54,4142.5 h60
  text "0" at 9189.92,4142.5 h60
M13 Component Bodies Top:
  text ".Layer_Name" at 418.57,-2692.59 h60
M14 Component Bodies Bottom:
  text ".Layer_Name" at 418.57,-2692.59 h60
M15 Courtyards Top:
  text ".Layer_Name" at 418.57,-2692.59 h60
M16 Courtyards Bottom:
  text ".Layer_Name" at 418.57,-2692.59 h60
Drill Drawing:
  lines w10: 5094,814 5682,814 ; 5177.67,1335.49 5232.92,1335.49 5205.29,1280.24 5177.67,1335.49 ; 5177.67,1418.38 5191.48,1418.38 5191.48,1404.56 5219.11,1404.56 5219.11,1418.38 5232.92,1418.38 5232.92,1446 5219.11,1446 5219.11,1459.81 5191.48,1459.81 5191.48,1446 5177.67,1446 5177.67,1418.38
  lines w12: 5127.57,1242.95 7988.1,1242.95 ; 5127.57,1491.59 7988.1,1491.59 ; 5465.44,1118.63 5465.44,1615.91 ; 5797.44,1118.63 5797.44,1615.91 ; 6434,1118.63 6434,1615.91 ; 6693.14,1118.63 6693.14,1615.91 ; 7068.3,1118.63 7068.3,1615.91 ; 5127.57,1118.63 7988.1,1118.63 7988.1,1615.91 5127.57,1615.91 5127.57,1118.63
  text "Symbol" at 5202.17,1528.88 h72
  text "Quantity" at 5502.73,1528.88 h72
  text "Finished Hole Size" at 5834.73,1528.88 h72
  text "Plated" at 6471.3,1528.88 h72
  text "Hole Type" at 6730.44,1528.88 h72
  text "Drill Layer Pair" at 7105.59,1528.88 h72
  text "7" at 5502.73,1404.56 h60
  text "7.87mil (0.200mm)" at 5834.73,1404.56 h60
  text "PTH" at 6471.3,1404.56 h60
  text "Round" at 6730.44,1404.56 h60
  text "L1-Top Layer - L6-Bottom Layer" at 7105.59,1404.56 h60
  text "111" at 5502.73,1280.24 h60
  text "8.00mil (0.203mm)" at 5834.73,1280.24 h60
  text "PTH" at 6471.3,1280.24 h60
  text "Round" at 6730.44,1280.24 h60
  text "L1-Top Layer - L6-Bottom Layer" at 7105.59,1280.24 h60
  text "118 Total" at 5502.73,1155.92 h60
  text "DRILL TOLERANCE" at 5099,832 h40
  text "FOR 7.87MIL DRILL +0/- 7.87 MIL" at 5201,711 h40
  text "FOR 8MIL DRILL +0/- 8 MIL" at 5198,642 h40
  text ".Layer_Name" at 418.57,-2692.59 h60
M17 Embedded Cavity:
  text ".Layer_Name" at 418.57,-2692.59 h60
M18 Embedded Assembly:
  text ".Layer_Name" at 418.57,-2692.59 h60
M19 Embedded Keepout:
  text ".Layer_Name" at 418.57,-2692.59 h60

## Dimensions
-157.48,826.77 to -157.48,39.37 on M2 Board Dimensions
-157.48,235.24 to -157.48,187.99 on M2 Board Dimensions
-157.48,826.77 to 0,866.14 on M2 Board Dimensions
-157.48,39.37 to 0,0 on M2 Board Dimensions
2991.58,866.14 to 2991.18,0 on M2 Board Dimensions
2991.58,486.9 to 2991.58,379.24 on M2 Board Dimensions
2991.58,866.14 to -157.48,826.77 on M2 Board Dimensions
-158.43,-2234.09 to 841.57,-2234.09 on M2 Board Dimensions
